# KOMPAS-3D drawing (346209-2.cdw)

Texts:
  Шарівський Я. В.
  ПолтНТУ 2009
  Текст на чертеже
  Размерные надписи
  Шероховатость
  Линия-выноска #1
  Линия-выноска #2
  Линия-выноска #3
  Отклонения формы и база
  Заголовок таблицы
  Ячейка таблицы
  Стрелка вида
  Обозначение изменения
  Фигурная скобка
  Номер узла
  Марка координационной оси
  VRCB
  Выносная надпись
  Обозначение узла
  Марка/позиционное обозначение с линией-выноской
  Марка/позиционное обозначение на линии
  Марка/позиционное обозначение без линии-выноски
Dimensions and other numbers on the sheet: 7; 1; 0; 2; 3; 4; 5; 6; 8; 9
